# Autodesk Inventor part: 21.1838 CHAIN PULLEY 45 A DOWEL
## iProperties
Created: 2007-05
Part Number: 21.1838 CHAIN PULLEY 45 A DOWEL
Material: Steel
Document SubType Name: Modeling
Designer: Andy Moles
Density: 7.85 g/cm^3
Author: Andy Moles
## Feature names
1. Extrusion1
2. Chamfer1
3. Chamfer2
